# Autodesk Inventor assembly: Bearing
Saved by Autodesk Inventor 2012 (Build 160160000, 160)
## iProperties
Created: 2011-12
Part Number: Bearing
Document SubType Name: Assembly
Designer: Admin
ClientObjectVersion: 1
Author: Admin
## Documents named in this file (2)
- C:\Documents and Settings\All Users\Autodesk Learning\Inventor 2009\Advanced Assembly and Machine Design\Workspace\GearBox-A\Design Accelerator\Bearing3.iam
- C:\Documents and Settings\All Users\Autodesk Learning\Inventor 2009\Advanced Assembly and Machine Design\Libraries\Content Center Files\en-US\DIN 618 - T1  HK\DIN 618 - HK3012 - 30 x 37 x 12.ipt
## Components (1 placed, 1 different names)
1. DIN 618 - T1 HK HK3012 - 30 x 37 x 12:1
